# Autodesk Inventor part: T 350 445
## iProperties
Company: Mayer & Müller AG Schaltgeräte
Created: 2006-03
Part Number: T 350 445
Material: 2.0060.10
Document SubType Name: Sheet Metal
Designer: I.Baliuc
Description: Strombald
Density: 8.94 g/cm^3
Sheet Metal Rule: Standard
HalbzeugNorm: DIN 1759
Abmessung: Band 120x0,15/0,1 ;Band 120x0,3
Author: T.Messerschmitt
Revision Number: 350445
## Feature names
1. Bohrung_Ø18 [Hole]
2. Bohrung_Ø13.5 [Hole]
3. Grobblech1
4. Biegung1
5. ExtrusionAbwicklung2
